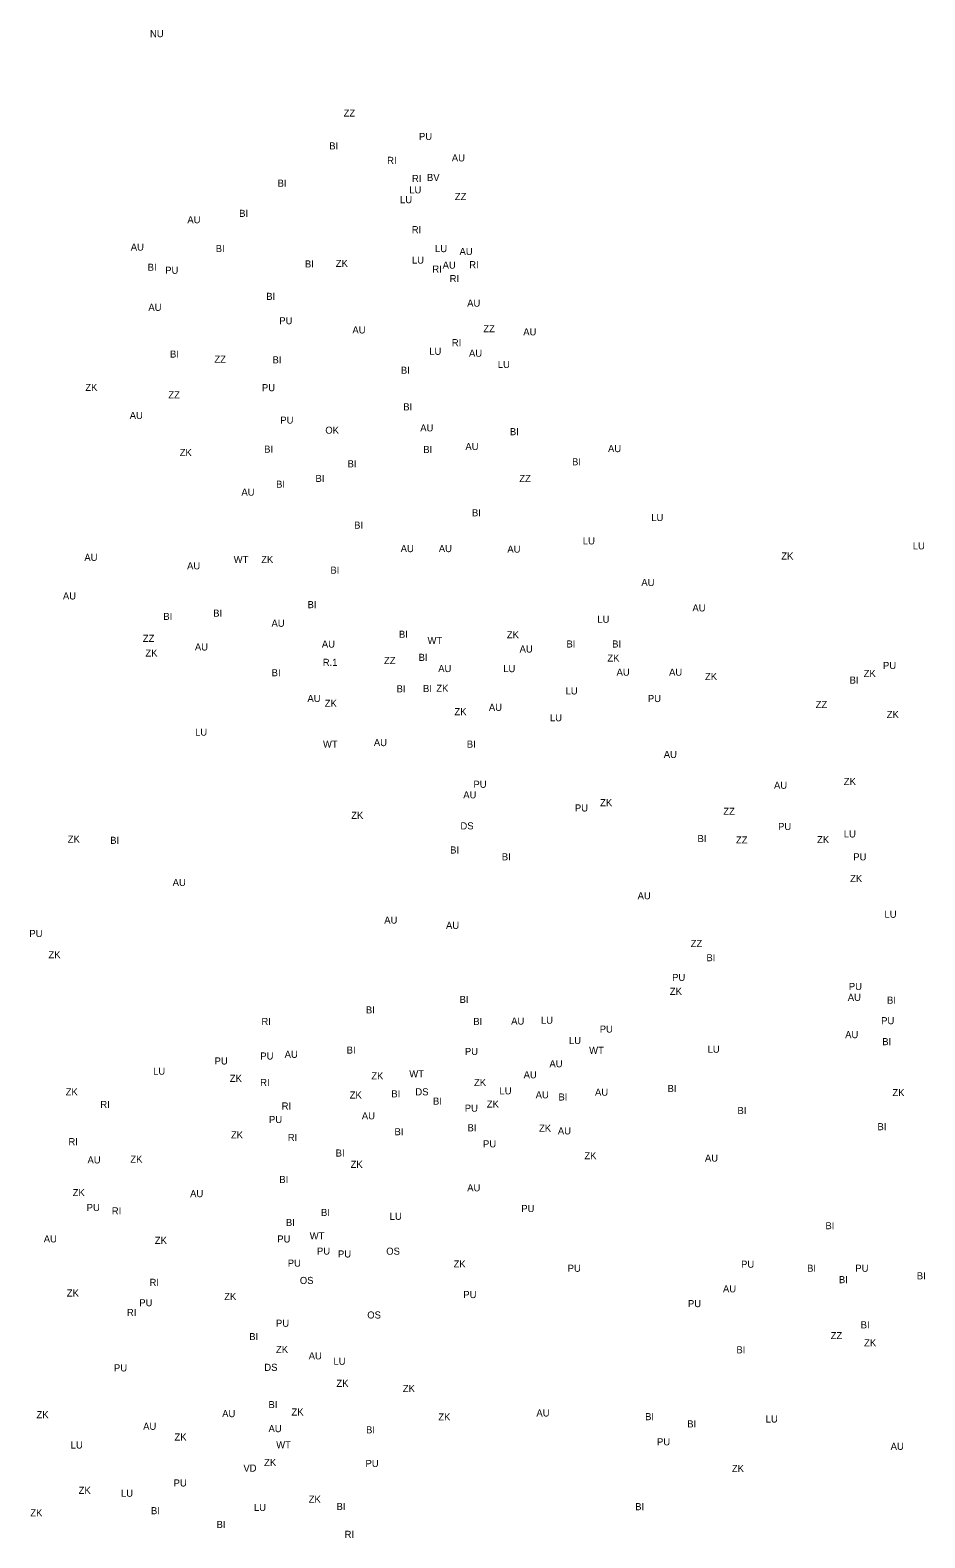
# Model space of a CAD drawing. Extents: x -439151 to -433911, y -1129946 to -1121460.
# Drawn here: x -437792 to -436527, y -1123590 to -1121460 of the extents above; entities that cross this region are included whole.
import ezdxf

# ---------------------------------------------------------------- set-up
doc = ezdxf.new("R2010")
doc.units = 0
doc.layers.add('POPIS PRESTAVBA', color=7, linetype='Continuous')
doc.layers.add('ZASTAVITELNA PLOCHA', color=7, linetype='Continuous')

msp = doc.modelspace()

# ---------------------------------------------------------------- texts
at = {"layer": 'POPIS PRESTAVBA'}
for s, p in [('NU', (-437622.2, -1121469.9)), ('ZZ', (-437348.6, -1121582.1)), ('PU', (-437242, -1121615.1)), ('BI', (-437368.8, -1121628.5)), ('RI', (-437287, -1121648.9)), ('AU', (-437195.6, -1121645.4)), ('BI', (-437441.8, -1121681.2)), ('RI', (-437251.8, -1121674.6)), ('BV', (-437230.7, -1121673)), ('LU', (-437255.7, -1121690.6)), ('ZZ', (-437191.3, -1121700)), ('BI', (-437496.2, -1121723.8)), ('LU', (-437268.8, -1121704.5)), ('AU', (-437569.4, -1121732.8)), ('RI', (-437252.2, -1121746.8)), ('AU', (-437649.4, -1121771.4)), ('BI', (-437529.3, -1121773.5)), ('LU', (-437219.3, -1121773.6)), ('AU', (-437184.7, -1121777.6)), ('BI', (-437625.5, -1121800)), ('PU', (-437600.7, -1121804.2)), ('ZK', (-437359.6, -1121794.5)), ('LU', (-437252, -1121789.8)), ('RI', (-437223.1, -1121802.5)), ('AU', (-437208.6, -1121796.9)), ('RI', (-437171, -1121796.3)), ('RI', (-437198.6, -1121816)), ('BI', (-437457.9, -1121841.1)), ('AU', (-437173.9, -1121850.6)), ('AU', (-437624.5, -1121856.6)), ('PU', (-437439.5, -1121875.5)), ('AU', (-437336.1, -1121888.5)), ('ZZ', (-437151.1, -1121886.8)), ('AU', (-437094.6, -1121891.2)), ('RI', (-437195.6, -1121906.5)), ('BI', (-437593.9, -1121922.6)), ('ZZ', (-437531.2, -1121929.9)), ('BI', (-437449, -1121930.8)), ('LU', (-437227.5, -1121918.7)), ('AU', (-437171.3, -1121921.4)), ('BI', (-437267.6, -1121945.5)), ('LU', (-437130.6, -1121937.2)), ('ZK', (-437713.6, -1121969.7)), ('ZZ', (-437596.3, -1121980.2)), ('BI', (-437264.2, -1121997.2)), ('AU', (-437650.9, -1122009.3)), ('PU', (-437438, -1122015.9)), ('AU', (-437240.2, -1122026.9)), ('BI', (-437113.5, -1122032.3)), ('ZK', (-437580.2, -1122061.8)), ('BI', (-437460.9, -1122056.9)), ('BI', (-437235.9, -1122057.4)), ('AU', (-437176.4, -1122053.2)), ('AU', (-436974.8, -1122056.2)), ('BI', (-437342.9, -1122077.7)), ('BI', (-437025.6, -1122074.8)), ('BI', (-437444, -1122106.6)), ('ZZ', (-437100.2, -1122098.4)), ('AU', (-437493, -1122117.7)), ('BI', (-437167.1, -1122146.9)), ('LU', (-436913.7, -1122153.6)), ('LU', (-437010.4, -1122186.6)), ('AU', (-437715, -1122209.9)), ('WT', (-437503.9, -1122212.8)), ('ZK', (-437465, -1122212.9)), ('AU', (-437267.9, -1122197.5)), ('AU', (-437214, -1122197.5)), ('AU', (-437117.1, -1122198.2)), ('ZK', (-436729.9, -1122208)), ('LU', (-436544, -1122193.6)), ('AU', (-437569.8, -1122221.8)), ('BI', (-437367.2, -1122227.9)), ('AU', (-436927.7, -1122245.4)), ('AU', (-437745.3, -1122264.4)), ('BI', (-437399.5, -1122276.7)), ('BI', (-437603.3, -1122293.3)), ('BI', (-437532.9, -1122288.7)), ('LU', (-436989.9, -1122297.3)), ('AU', (-436855.5, -1122281.3)), ('AU', (-437450.5, -1122303)), ('BI', (-437270.3, -1122318.6)), ('ZK', (-437117.8, -1122319.2)), ('ZZ', (-437632.3, -1122324.3)), ('AU', (-437558.8, -1122336.5)), ('AU', (-437379.3, -1122332.4)), ('WT', (-437229.9, -1122327.4)), ('AU', (-437099.8, -1122339.4)), ('BI', (-437033.6, -1122332.3)), ('BI', (-436969, -1122332.3)), ('ZK', (-437628.7, -1122345.1)), ('ZZ', (-437291.5, -1122355.7)), ('BI', (-437242.5, -1122351.2)), ('ZK', (-436975.7, -1122352.2)), ('PU', (-436586.1, -1122362.7)), ('BI', (-437450.2, -1122372.9)), ('AU', (-437214.8, -1122367)), ('LU', (-437122.9, -1122367.1)), ('AU', (-436962.7, -1122372.1)), ('AU', (-436888.5, -1122372.1)), ('ZK', (-436837.7, -1122378.2)), ('BI', (-436633.3, -1122383.3)), ('ZK', (-436613.4, -1122373.9)), ('BI', (-437273.6, -1122395.6)), ('BI', (-437236.3, -1122395.2)), ('ZK', (-437217.5, -1122394.9)), ('LU', (-437034.8, -1122398.6)), ('AU', (-437399.7, -1122409.2)), ('ZK', (-437375.2, -1122416.1)), ('AU', (-437143.2, -1122421.8)), ('PU', (-436918.5, -1122409.4)), ('ZZ', (-436681.2, -1122417.7)), ('ZK', (-437191.9, -1122427.9)), ('LU', (-437056.9, -1122436.5)), ('ZK', (-436580.8, -1122431.9)), ('LU', (-437558.5, -1122456.8)), ('WT', (-437377.7, -1122473.7)), ('AU', (-437305.8, -1122471.6)), ('BI', (-437174.4, -1122473.8)), ('AU', (-436896, -1122488.3)), ('PU', (-437165, -1122530.5)), ('AU', (-436740.2, -1122531.9)), ('ZK', (-436641.5, -1122526.5)), ('AU', (-437179.4, -1122545.4)), ('ZK', (-437337.8, -1122574.4)), ('PU', (-437021.6, -1122564)), ('ZK', (-436986, -1122556.5)), ('ZZ', (-436811.9, -1122568.7)), ('DS', (-437183.4, -1122589.3)), ('PU', (-436734.4, -1122590.2)), ('ZK', (-437738.5, -1122608.1)), ('BI', (-437678.5, -1122609.7)), ('BI', (-436848.3, -1122607.3)), ('ZZ', (-436794, -1122609.2)), ('ZK', (-436679.3, -1122608.7)), ('LU', (-436641.5, -1122600.7)), ('BI', (-437198, -1122623.4)), ('PU', (-436628.1, -1122633.1)), ('AU', (-437590.2, -1122669.3)), ('ZK', (-436632.6, -1122663.7)), ('AU', (-436933, -1122688)), ('AU', (-437291.1, -1122722.4)), ('LU', (-436584, -1122714.2)), ('PU', (-437792.7, -1122741.4)), ('AU', (-437203.8, -1122729.9)), ('ZZ', (-436858, -1122755.6)), ('ZK', (-437765.7, -1122771.4)), ('BI', (-436835.7, -1122775.6)), ('PU', (-436884.2, -1122803.4)), ('ZK', (-436887.4, -1122823.1)), ('AU', (-436635.9, -1122831.6)), ('PU', (-436634.4, -1122816.2)), ('BI', (-437317, -1122849.4)), ('BI', (-437184.6, -1122834.5)), ('BI', (-436580.4, -1122835.6)), ('RI', (-437464.7, -1122865.6)), ('AU', (-437111.7, -1122865.1)), ('LU', (-437069.6, -1122863.9)), ('PU', (-436588.7, -1122864.6)), ('LU', (-437030, -1122892.6)), ('PU', (-436986.5, -1122876.4)), ('AU', (-436639.6, -1122884.3)), ('BI', (-436587.1, -1122894.2)), ('PU', (-437466.3, -1122914.5)), ('AU', (-437431.9, -1122912.1)), ('BI', (-437344.2, -1122906.1)), ('WT', (-437001.5, -1122906.5)), ('LU', (-436834.1, -1122904.9)), ('LU', (-437617.8, -1122935.9)), ('PU', (-437530.9, -1122921.5)), ('AU', (-437057.6, -1122925.4)), ('ZK', (-437509.4, -1122946.1)), ('RI', (-437466.5, -1122951.8)), ('ZK', (-437309.4, -1122942.6)), ('WT', (-437255.7, -1122939.7)), ('ZK', (-437164.2, -1122951.9)), ('AU', (-437094.1, -1122941)), ('ZK', (-437741.4, -1122965.2)), ('ZK', (-437339.9, -1122969.6)), ('BI', (-437281.1, -1122967.9)), ('DS', (-437247.1, -1122965.1)), ('BI', (-437222.2, -1122978.2)), ('LU', (-437128.2, -1122963.7)), ('AU', (-437077.1, -1122969.3)), ('BI', (-437044.9, -1122972.4)), ('AU', (-436993.2, -1122965.6)), ('BI', (-436890.6, -1122960.4)), ('ZK', (-436572.8, -1122966.2)), ('RI', (-437692.4, -1122983)), ('RI', (-437436.1, -1122985.1)), ('AU', (-437322.8, -1122999)), ('PU', (-437177.3, -1122988.2)), ('ZK', (-437146.1, -1122982.4)), ('BI', (-436791.8, -1122991.5)), ('PU', (-437454, -1123004.2)), ('BI', (-437276.6, -1123021.5)), ('BI', (-437173.4, -1123015.9)), ('ZK', (-437072.3, -1123016.5)), ('AU', (-437045.7, -1123020.3)), ('BI', (-436593.9, -1123014.4)), ('RI', (-437737.5, -1123035.5)), ('ZK', (-437507.8, -1123026)), ('RI', (-437427.5, -1123029.6)), ('PU', (-437151.5, -1123038.6)), ('AU', (-437710.6, -1123061.3)), ('ZK', (-437650, -1123060.2)), ('BI', (-437359.7, -1123051.6)), ('ZK', (-437008.2, -1123055.4)), ('AU', (-436837.8, -1123058.7)), ('ZK', (-437338.7, -1123067.6)), ('ZK', (-437731.5, -1123107.5)), ('BI', (-437439.4, -1123088.9)), ('AU', (-437173.8, -1123100.7)), ('PU', (-437711.7, -1123128.6)), ('AU', (-437565.5, -1123109)), ('PU', (-437097.4, -1123130)), ('RI', (-437676.2, -1123133.4)), ('BI', (-437430.1, -1123149.7)), ('BI', (-437380.5, -1123135.5)), ('LU', (-437283.4, -1123141)), ('WT', (-437396.4, -1123168.7)), ('BI', (-436667.5, -1123154.3)), ('AU', (-437772.4, -1123172.9)), ('ZK', (-437615.4, -1123175)), ('PU', (-437442.3, -1123173)), ('PU', (-437386.2, -1123190.1)), ('OS', (-437288.3, -1123190.3)), ('PU', (-437356.5, -1123194.2)), ('ZK', (-437193.1, -1123208.3)), ('PU', (-437031.8, -1123214.4)), ('PU', (-436786.7, -1123208.7)), ('BI', (-436693.4, -1123214.4)), ('PU', (-436625.2, -1123214.4)), ('RI', (-437622.9, -1123234.3)), ('OS', (-437410.4, -1123231.6)), ('BI', (-436648.4, -1123230.5)), ('BI', (-436538.3, -1123225.1)), ('ZK', (-437739.8, -1123249.4)), ('ZK', (-437517.3, -1123254.3)), ('PU', (-437179.3, -1123251.6)), ('AU', (-436812.3, -1123243.4)), ('RI', (-437654.8, -1123277)), ('PU', (-437637.4, -1123263.1)), ('PU', (-436861.8, -1123264.4)), ('BI', (-436617.6, -1123294.4)), ('BI', (-437482, -1123311)), ('ZZ', (-436660.1, -1123309.6)), ('ZK', (-436612.8, -1123319.7)), ('ZK', (-437444.1, -1123329.1)), ('AU', (-437397.9, -1123338.2)), ('BI', (-436793.3, -1123329.6)), ('PU', (-437673.1, -1123355.2)), ('DS', (-437460.6, -1123354.4)), ('LU', (-437362.9, -1123345.8)), ('ZK', (-437358.7, -1123377)), ('ZK', (-437264.8, -1123384.3)), ('ZK', (-437782.6, -1123421.3)), ('AU', (-437520.2, -1123419.8)), ('BI', (-437454.8, -1123407.1)), ('ZK', (-437422.2, -1123417.5)), ('ZK', (-437214.7, -1123424.5)), ('AU', (-437076, -1123418.9)), ('BI', (-436922.4, -1123424.1)), ('LU', (-436751.9, -1123427.4)), ('AU', (-437631.9, -1123437.7)), ('AU', (-437454.7, -1123441)), ('BI', (-436862.8, -1123434.4)), ('LU', (-437734.3, -1123464.2)), ('ZK', (-437587.6, -1123452.9)), ('WT', (-437443.8, -1123463.9)), ('PU', (-436905.5, -1123459.6)), ('AU', (-436575.3, -1123466)), ('ZK', (-437460.9, -1123488.8)), ('PU', (-437317.6, -1123490.2)), ('VD', (-437490.2, -1123496.8)), ('ZK', (-436799.7, -1123497.3)), ('ZK', (-437723.1, -1123528.2)), ('LU', (-437663.2, -1123532.3)), ('PU', (-437588.8, -1123517.8)), ('LU', (-437475.3, -1123552.3)), ('ZK', (-437397.9, -1123540.8)), ('BI', (-437358.5, -1123551)), ('BI', (-436936.4, -1123551.3)), ('ZK', (-437791.4, -1123560)), ('BI', (-437620.8, -1123557)), ('BI', (-437528.1, -1123576.4)), ('RI', (-437347.1, -1123590.4))]:
    msp.add_text(s, height=10, dxfattribs=at).set_placement(p)
at = {"layer": 'ZASTAVITELNA PLOCHA'}
for s, p in [('BI', (-437403.2, -1121795.3)), ('PU', (-437464, -1121970.1)), ('OK', (-437374.4, -1122030.2)), ('BI', (-437388.3, -1122098.3)), ('BI', (-437333.7, -1122164.3)), ('R.1', (-437378, -1122358.2)), ('BI', (-437124.9, -1122633)), ('BI', (-437165.2, -1122865.7)), ('PU', (-437177.1, -1122908)), ('PU', (-437427.5, -1123207.1)), ('PU', (-437444.1, -1123292.1)), ('OS', (-437315.1, -1123280.4)), ('BI', (-437316.8, -1123442.7))]:
    msp.add_text(s, height=10, dxfattribs=at).set_placement(p)

doc.saveas('drawing.dxf')
